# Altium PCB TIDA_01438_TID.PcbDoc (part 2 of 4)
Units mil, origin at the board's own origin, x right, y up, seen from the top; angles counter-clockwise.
Board outline 6250 x 2150 mil, 4 copper layers (Top Layer, V-, V+, Bottom Layer), stack 61.6 mil thick; 360 components, 217 nets, 1141 pads, 401 vias.
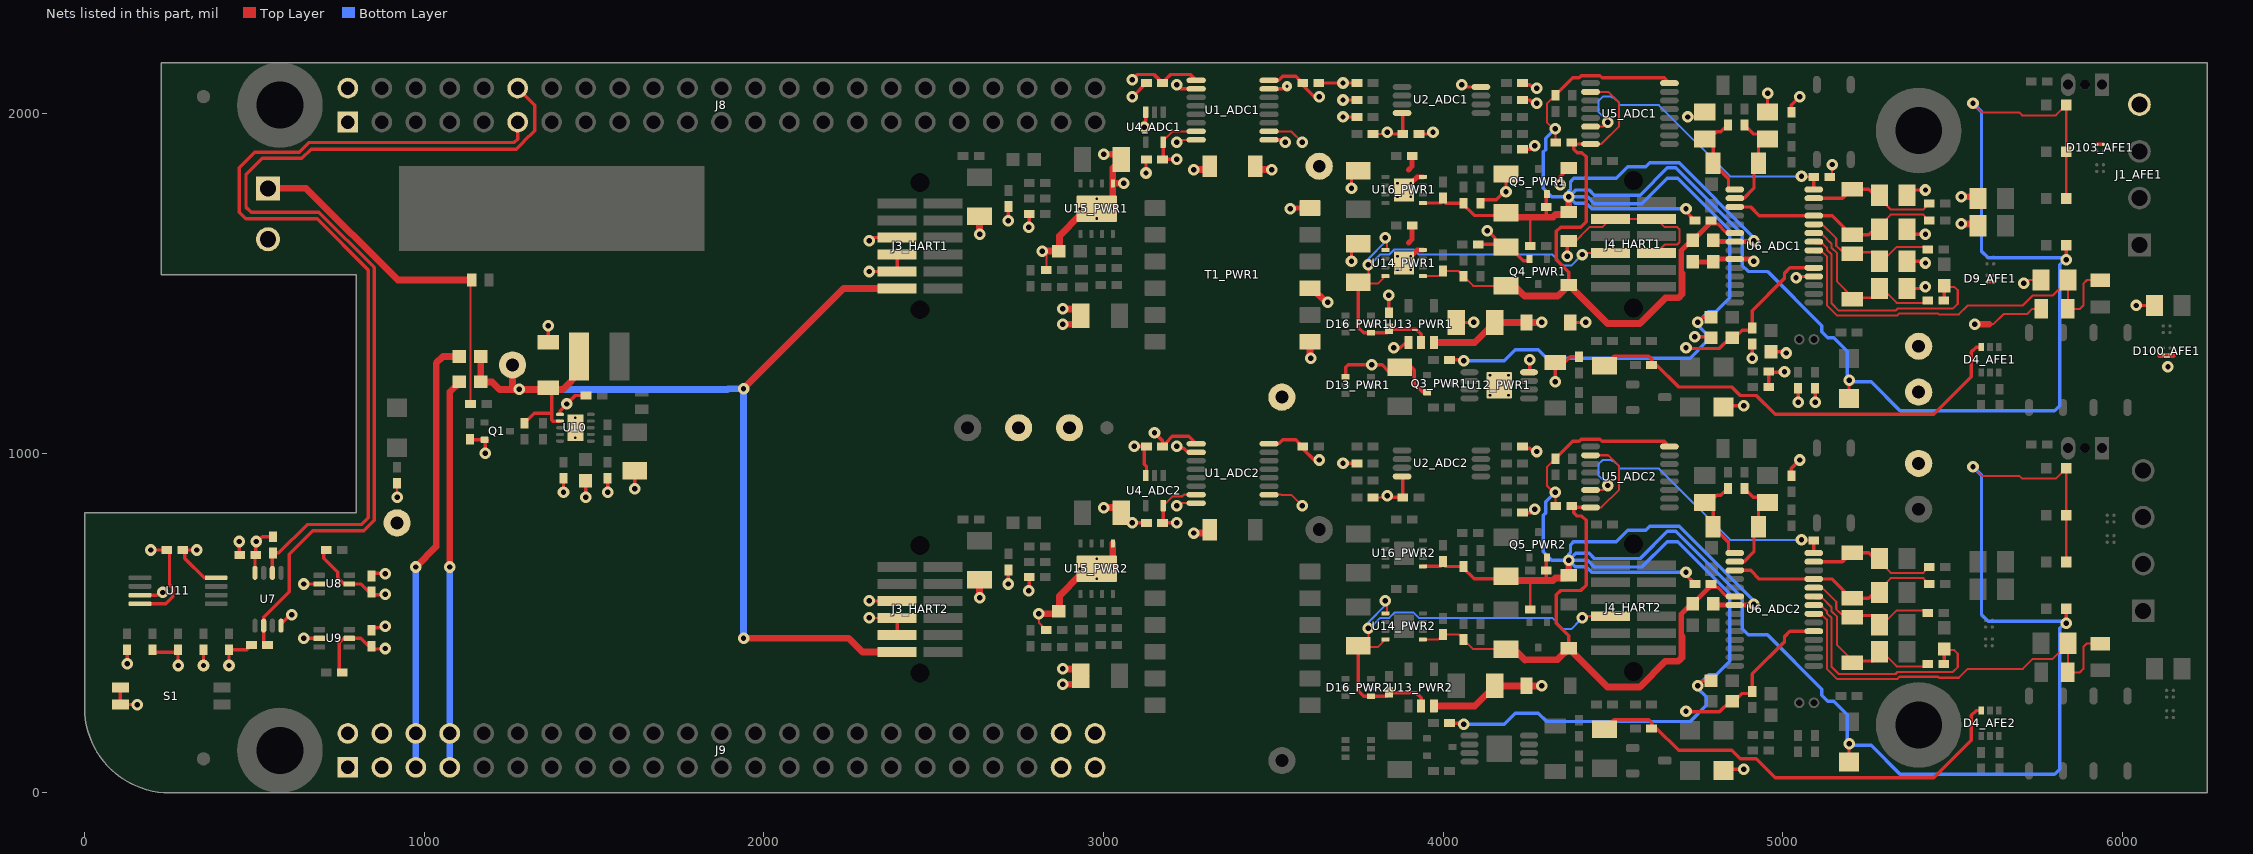
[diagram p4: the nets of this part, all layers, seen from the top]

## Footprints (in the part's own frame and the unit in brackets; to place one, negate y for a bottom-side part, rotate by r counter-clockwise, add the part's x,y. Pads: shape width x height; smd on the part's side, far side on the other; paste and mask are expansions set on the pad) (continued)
Samtec_TFM-106-02-x-D-A [mm] "Header(Shrouded), 1.27mm, 6x2, SMT"
  rect 2.92x0.74 smd: 1(-1.715,3.175) 2(1.715,3.175) 3(-1.715,1.905) 4(1.715,1.905) 5(-1.715,0.635) 6(1.715,0.635) 7(-1.715,-0.635) 8(1.715,-0.635) 9(-1.715,-1.905) 10(1.715,-1.905) 11(-1.715,-3.175) 12(1.715,-3.175)
  round 0 hole 1.42 unplated: MH1(0,4.765) MH2(0,-4.765)
  silkscreen extent -3.2,-5.4 2.86,5.4, body extent -2.98,-5.4 2.98,5.4, height 5.74
SOD-123 [mm] "On Semi recommended land pattern"
  rect 0.915x1.22 smd: 1(-1.637,0) 2(1.637,0)
  silkscreen extent -2.74,-1.17 2.03,1.17, body extent -1.93,-0.9 1.93,0.9, height 1.35
SOT-23 [mm] "SOT23, 3-Leads, Body 2.9x1.3mm, Pitch 0.95mm, Lead Span 2.5mm, IPC Medium Density"
  rrect50% 1x0.6 smd: 1(-1.2,0.95) 2(-1.2,-0.95) 3(1.2,0)
  silkscreen extent -1.63,-1.5 0.7,1.5, body extent -1.16,-1.45 1.21,1.45, height 1
SOT-323 [mm] "Diodes Inc recommended land pattern.  2016-02-24"
  rrect21% 0.6x0.47 smd: 1(-0.95,0.65) 2(-0.95,-0.65) 3(0.95,0)
  silkscreen extent -1.14,-1.22 0.77,1.22, body extent -1.13,-1.13 1.12,1.12, height 1.13
SOT-363 [mm]
  rect 0.6x0.42 smd mask+0.051: 1(-0.95,0.65) 2(-0.95,0) 3(-0.95,-0.65) 4(0.95,-0.65) 5(0.95,0) 6(0.95,0.65)
  silkscreen extent -0.38,-1.02 0.38,1.02, body extent -1.1,-1.1 1.1,1.1, height 1.12
SW_416131160802 [mm] "SMD, 4-Leads, Body 5.6x3.58mm, Pitch 1.27mm"
  rect 1.27x0.76 smd: 1(-3.81,0.635) 2(-3.81,-0.635) 3(3.81,-0.635) 4(3.81,0.635)
  silkscreen extent -2.8,-1.79 2.8,2.1, body extent -4,-1.79 4,1.79, height 2.1
TESTPOINT [mil]
  round 80 hole 37.99: 1(0,0)
TI_Stacked_SolderMask_Small [mil]
  rect 900x250 smd paste-125 mask-125: 0(0,0)
TSSOP-8 [mm] "TSSOP, 8-Leads, Body 3.1x4.5mm (max), Pitch 0.65mm, IPC Medium Density"
  rrect50% 1.7x0.35 smd: 1(-2.85,0.975) 2(-2.85,0.325) 3(-2.85,-0.325) 4(-2.85,-0.975) 5(2.85,-0.975) 6(2.85,-0.325) 7(2.85,0.325) 8(2.85,0.975)
  silkscreen extent -2.98,-1.55 1.6,1.82, body extent -3.2,-1.55 3.2,1.55, height 1.07
WE-LQS_4018 [mm] "SMD, 2-Leads, Body 4x4mm"
  rect 1.5x3.6 smd: 1(-1.525,0) 2(1.525,0)
  silkscreen extent -0.5,-2 0.5,2, body extent -2,-2 2,2, height 1.8
WL_SMCW_GREEN_1206 [mm] "SMD, 2-Leads, Body 3.2x1.6mm, Pitch 3mm"
  rect 1.4x1.5 smd: 1(-1.5,0) 2(1.5,0)
  silkscreen extent -2.9,-1.1 2.2,1.1, body extent -1.6,-0.85 1.6,0.85, height 0.78
WL_SMCW_RED_1206 [mm] "SMD, 2-Leads, Body 3.2x1.6mm, Pitch 3mm"
  rect 1.4x1.5 smd: 1(-1.5,0) 2(1.5,0)
  silkscreen extent -2.9,-1.1 2.2,1.1, body extent -1.6,-0.85 1.6,0.85, height 0.78
Wurth_750315856 [mm] "SMT, 12-Leads, Body 12.85x12.95mm, Pitch 2mm"
  rrect9% 1.57x1.17 smd: 1(-5.79,5) 2(-5.79,3) 3(-5.79,1) 4(-5.79,-1) 5(-5.79,-3) 6(-5.79,-5) 7(5.79,-5) 8(5.79,-3) 9(5.79,-1) 10(5.79,1) 11(5.79,3) 12(5.79,5)
  silkscreen extent -5.3,-6.48 5,6.48, body extent -6.42,-6.47 6.43,6.48, height 6.35
YZF0004-C01 [mm] "BGA, 4-Balls, Body 1.062x1.116mm, Pitch 0.5mm"
  round 0.245 smd paste-0.125: A1(-0.25,0.25) A2(0.25,0.25) B1(-0.25,-0.25) B2(0.25,-0.25)
  silkscreen extent -0.68,-0.65 0.67,0.65, body extent -0.57,-0.55 0.57,0.55, height 0.63

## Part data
C1_ADC1 C1_ADC2 C2_ADC1 C2_ADC2 C3_ADC1 C3_ADC2 C4_ADC1 C4_ADC2 C5_ADC1 C5_ADC2 C7_ADC1 C7_ADC2 C9_ADC1 C9_ADC2 C10_ADC1 C10_ADC2 C26_AFE1 C26_AFE2 C31 C32 C33 C34 C36 C38 C43_PWR1 C43_PWR2 C54_PWR1 C54_PWR2 C56_PWR1 C56_PWR2: "CAP, CERM, 0.1 µF, 50 V, +/- 10%, X7R, 0402"
C6_ADC1 C6_ADC2 C8_ADC1 C8_ADC2 C14_ADC1 C14_ADC2 C15_ADC1 C15_ADC2 C16_ADC1 C16_ADC2 C37: "CAP, CERM, 1 µF, 16 V, +/- 10%, X7R, 0603"
C11_ADC1 C11_ADC2: "CAP, CERM, 4700 pF, 25 V, +/- 5%, C0G/NP0, 0603"
C12_ADC1 C12_ADC2 C13_ADC1 C13_ADC2: "CAP, CERM, 33 pF, 25 V, +/- 5%, C0G/NP0, 0402"
C17_AFE1 C17_AFE2 C19_AFE1 C19_AFE2 C22_AFE1 C22_AFE2 C25_AFE1 C25_AFE2 C28_AFE1 C28_AFE2 C30_AFE1 C30_AFE2: "CAP, CERM, 8200 pF, 50 V, +/- 5%, C0G/NP0, 0805"
C18_AFE1 C18_AFE2 C24_AFE1 C24_AFE2 C29_AFE1 C29_AFE2: "CAP, CERM, 0.1 µF, 50 V, +/- 5%, C0G/NP0, 1206_190"
C20_AFE1 C20_AFE2 C23_AFE1 C23_AFE2 C27_AFE1 C27_AFE2: "CAP, CERM, 0.01 µF, 100 V, +/- 10%, X7R, 0805"
C21_AFE1 C21_AFE2: "CAP, CERM, 5600 pF, 50 V, +/- 5%, C0G/NP0, 0805"
C35 C40_PWR1 C40_PWR2: "CAP, CERM, 4.7 µF, 50 V, +/- 20%, X7R, 1206_190"
C39 C41_PWR1 C41_PWR2 C53_PWR1 C53_PWR2 C55_PWR1 C55_PWR2: "CAP, CERM, 2.2 µF, 50 V, +/- 10%, X7R, 1206"
C42_PWR1 C42_PWR2: "CAP, CERM, 270 pF, 50 V, +/- 10%, X7R, 0402"
C44_PWR1 C44_PWR2 C46_PWR1 C46_PWR2 C47_PWR1 C47_PWR2 C52_PWR1 C52_PWR2 C58_PWR1 C58_PWR2: "CAP, CERM, 10 µF, 16 V, +/- 20%, X7R, 1206"
C45_PWR1 C45_PWR2 C48_PWR1 C48_PWR2 C49_PWR1 C49_PWR2 C51_PWR1 C51_PWR2 C59_PWR1 C59_PWR2: "CAP, CERM, 0.01 µF, 25 V, +/- 10%, X7R, 0402"
C50_PWR1 C50_PWR2: "CAP, CERM, 3300 pF, 50 V, +/- 10%, X7R, 0402"
C57_PWR1 C57_PWR2: "CAP, CERM, 10 µF, 25 V, +/- 10%, X7R, 1206"
C60_PWR1 C60_PWR2: "CAP, CERM, 1 µF, 25 V, +/- 10%, X7R, 0603"
C61_PWR1 C61_PWR2: "CAP, CERM, 1000 pF, 2000 V, +/- 10%, X7R, 1206_190"
D1_ADC1 D1_ADC2 D3_AFE1 D3_AFE2 D6_AFE1 D6_AFE2 D8_AFE1 D8_AFE2: "LED, Blue, SMD"
D2_ADC1 D2_ADC2: "LED, Red, SMD"
D4_AFE1 D4_AFE2 D13_PWR1 D13_PWR2 D16_PWR1 D16_PWR2: "Diode, Schottky, 70 V, 0.07 A, SOT-363"
D5_AFE1 D5_AFE2 D7_AFE1 D7_AFE2 D9_AFE1 D9_AFE2 D100_AFE1 D100_AFE2 D101_AFE1 D101_AFE2 D103_AFE1 D103_AFE2: "33V Precision Surge Protection Clamp, YZF0004-C01 (DSBGA-4)"
D10 D19_PWR1 D19_PWR2 D20: "Diode, Schottky, 35 V, 0.2 A, 0603 Diode"
D11 D12_PWR1 D12_PWR2 D14_PWR1 D14_PWR2: "LED, Green, SMD"
D15_PWR1 D15_PWR2 D17_PWR1 D17_PWR2: "Diode, Zener, 3.6 V, 500 mW, SOD-123"
D18_PWR1 D18_PWR2: "Diode, Zener, 2.7 V, 500 mW, SOD-123"
FID1 FID2 FID3: "Fiducial mark.  There is nothing to buy or mount."
J1_AFE1 J1_AFE2: "Terminal Block, 4x1, 3.5mm, Green, R/A, TH"
J2: "Terminal Block, 2x1, 3.81mm, R/A, TH"
J3_HART1 J3_HART2 J4_HART1 J4_HART2: "Header(Shrouded), 1.27mm, 6x2, Tin, SMT"
J8 J9: "Female Connector, 2.54mm, 23x2, TH"
K1_AFE1 K1_AFE2 K2_AFE1 K2_AFE2 K3_AFE1 K3_AFE2: "Relay, SPST-NO (1 Form A), 0.1 A, 1.2 VDC, SMD"
L1: "Inductor, Wirewound, Ferrite, 10 µH, 1.2 A, 0.15 ohm, SMD"
L2_PWR1 L2_PWR2: "Inductor, Ferrite, 2.2 µH, 0.35 A, 0.38 ohm, SMD"
Logo1: library part TI_Logo, "Texas Instrument Corporate Signature"
Logo2: library part Pb-Free
MH1 MH2 MH3 MH4: library part "Mounting Hole (Imperial) with Pads", "PCB Mounting Hole"
Q1 Q3_PWR1 Q3_PWR2 Q4_PWR1 Q4_PWR2 Q5_PWR1 Q5_PWR2: "MOSFET, N-CH, 60 V, 0.31 A, SOT-323"
Q2_PWR1 Q2_PWR2: library part "BC856A-7-F, Diodes Inc.", "Transistor, PNP, 65 V, 0.01 A, SOT-23"
R1_ADC1 R1_ADC2 R37 R38: "RES, 6.65 k, 1%, 0.063 W, 0402"
R2_ADC1 R2_ADC2 R41: "RES, 261 k, 1%, 0.063 W, 0402"
R3_ADC1 R3_ADC2 R5_ADC1 R5_ADC2 R9_ADC1 R9_ADC2 R10_ADC1 R10_ADC2 R11_ADC1 R11_ADC2 R28 R29 R32 R33 R34 R35 R36 R39 R42 R47_PWR1 R47_PWR2 R51_PWR1 R51_PWR2 R53_PWR1 R53_PWR2 R58_PWR1 R58_PWR2 R61_PWR1 R61_PWR2: "RES, 47 k, 5%, 0.063 W, 0402"
R4_ADC1 R4_ADC2: "RES, 576 k, 1%, 0.063 W, 0402"
R6_ADC1 R6_ADC2: "RES, 340 k, 1%, 0.063 W, 0402"
R7_ADC1 R7_ADC2 R12_ADC1 R12_ADC2: "RES, 1.65 k, 1%, 0.063 W, 0402"
R8_ADC1 R8_ADC2 R45 R50_PWR1 R50_PWR2: "RES, 8.25 k, 1%, 0.063 W, 0402"
R13_ADC1 R13_ADC2: "RES, 475, 1%, 0.063 W, 0402"
R14_AFE1 R14_AFE2 R17_AFE1 R17_AFE2 R21_AFE1 R21_AFE2 R22_AFE1 R22_AFE2 R24_AFE1 R24_AFE2 R26_AFE1 R26_AFE2 R27_AFE1 R27_AFE2 R49_PWR1 R49_PWR2: "RES, 5.11 k, 1%, 0.063 W, 0402"
R15_AFE1 R15_AFE2 R20_AFE1 R20_AFE2 R23_AFE1 R23_AFE2: "RES, 49.9, 1%, 0.063 W, 0402"
R16_AFE1 R16_AFE2: "RES, 4.99 k, 0.01%, 0.1 W, 0603"
R18_AFE1 R18_AFE2: "RES, 82.5 k, 0.1%, 0.1 W, 0805"
R19_AFE1 R19_AFE2: "RES, 17.8 k, 0.1%, 0.1 W, 0805"
R25_AFE1 R25_AFE2: "RES, 27.4, 0.1%, 0.1 W, 0805"
R30 R31: "RES, 0, 5%, 0.1 W, 0603"
R40 R56_PWR1 R56_PWR2 R64_PWR1 R64_PWR2 R69_PWR1 R69_PWR2: "RES, 100 k, 1%, 0.063 W, 0402"
R43: "RES, 200 k, 1%, 0.063 W, 0402"
R44: "RES, 8.06 k, 1%, 0.063 W, 0402"
R46_PWR1 R46_PWR2: "RES, 20.5, 1%, 0.25 W, 1206"
R48_PWR1 R48_PWR2 R52_PWR1 R52_PWR2: "RES, 953 k, 1%, 0.063 W, 0402"
R54_PWR1 R54_PWR2: "RES, 931, 1%, 0.063 W, 0402"
R55_PWR1 R55_PWR2 R60_PWR1 R60_PWR2: "RES, 113 k, 1%, 0.063 W, 0402"
R57_PWR1 R57_PWR2 R59_PWR1 R59_PWR2: "RES, 169 k, 1%, 0.063 W, 0402"
R62_PWR1 R62_PWR2: "RES, 1.0, 5%, 0.063 W, 0402"
R63_PWR1 R63_PWR2: "RES, 422 k, 1%, 0.063 W, 0402"
R65_PWR1 R65_PWR2: "RES, 54.9 k, 1%, 0.063 W, 0402"
R66_PWR1 R66_PWR2: "RES, 73.2 k, 1%, 0.063 W, 0402"
R67_PWR1 R67_PWR2: "RES, 8.66 k, 1%, 0.063 W, 0402"
R68_PWR1 R68_PWR2: "RES, 7.68 k, 1%, 0.063 W, 0402"
S1: "Switch, SPST, Off-On, 2 Pos, SMD"
T1_PWR1 T1_PWR2: "Transformer, 120 uH, SMT"
TP1_ADC1 TP1_ADC2 TP2 TP3 TP4_AFE1 TP4_AFE2 TP5_AFE1 TP5_AFE2 TP6_AFE1 TP6_AFE2 TP7 TP8 TP10: "TEST POINT.  No entry in BOM."
U1_ADC1 U1_ADC2: "4242-VPK Small-Footprint and Low-Power Quad Channels Digital Isolators, DBQ0016A"
U2_ADC1 U2_ADC2: "Dual Comparator, PW0008A"
U3_ADC1 U3_ADC2: "0.5°C Accurate 2-Pin Digital NTC or PTC Thermistor Replacement, LPG0002A"
U4_ADC1 U4_ADC2: "Single Bus Buffer Gate With 3-State Output, DCK0005A"
U5_ADC1 U5_ADC2: "8-Bit Shift Register With Output Registers, PW0016A"
U6_ADC1 U6_ADC2: "32-Bit, Precision, 38-kSPS, Analog-to-Digital Converter (ADC) with Programmable Gain Amplifier (PGA) and Voltage Reference, PW0028A"
U7: "Dual 2-Input Exclusive-OR Gate, DCT0008A"
U8 U9: "Single 3-Input Positive-OR Gate, DCK0006A"
U10: "LOW INPUT BOOST CONVERTER WITH INTEGRATED POWER DIODE AND INPUT/OUTPUT ISOLATION, DSK0010A"
U11: "256K I2C CMOS Serial EEPROM, TSSOP-8"
U12_PWR1 U12_PWR2: "Single Output LDO, 50 mA, Adjustable 1.175 to 48 V Output, 7 to 50 V Input, 8-pin MSOP (DGN), -40 to 125 degC, Green (RoHS & no Sb/Br)"
U13_PWR1 U13_PWR2: "Single Output LDO, 150 mA, Fixed 3.3 V Output, 2.5 to 24 V Input, with Ultra-Low IQ, 5-pin SOT-23 (DBV), -40 to 125 degC, Green (RoHS & no Sb/Br)"
U14_PWR1 U14_PWR2: "+36V, +150mA, Ultralow-Noise, Positive LINEAR REGULATOR, DRB0008A"
U15_PWR1 U15_PWR2: "100V, 600mA Constant On-Time Synchronous Buck Regulator, NGU0008B"
U16_PWR1 U16_PWR2: "-35-V, -200-mA, Ultralow-Noise, Negative Linear Regulator, DRB0008A"
Y1_ADC1 Y1_ADC2: "Crystal, 7.3728MHz, 18pF, SMD"
ZZ1 ZZ2 ZZ3: library part AssemblyNote

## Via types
v1: diameter 34, hole 16, Top Layer to Bottom Layer, 337 vias
v2: diameter 19.68, hole 7.87, Top Layer to Bottom Layer, 36 vias
v3: diameter 39.37, hole 19.68, Top Layer to Bottom Layer, 24 vias
v4: diameter 30, hole 10, Top Layer to Bottom Layer, 4 vias

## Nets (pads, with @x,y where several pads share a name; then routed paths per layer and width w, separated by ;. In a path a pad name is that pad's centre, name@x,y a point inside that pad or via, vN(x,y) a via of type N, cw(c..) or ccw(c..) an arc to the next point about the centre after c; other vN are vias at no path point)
"4-20MA LOOP_AFE1": D4_AFE1.3 R46_PWR1.1 R49_PWR1.2 | length 1325.5
  Top Layer w10: R46_PWR1.1@4475,1257.09 4502.91,1285 4605,1285 4613.62,1276.38 R49_PWR1.2@4613.62,1260 4628,1260 4693,1195 4850,1195 4875,1170 4922.26,1170 4977.26,1115 5445,1115 5555,1225 5555,1297.99 5569.41,1312.4 D4_AFE1.3@5584.41,1312.4
"4-20MA LOOP_AFE2": D4_AFE2.3 R46_PWR2.1 R49_PWR2.2 | length 1325.5
  Top Layer w10: R46_PWR2.1@4475,187.09 4502.91,215 4605,215 4613.62,206.38 R49_PWR2.2@4613.62,190 4628,190 4693,125 4850,125 4875,100 4922.26,100 4977.26,45 5445,45 5555,155 5555,227.99 5569.41,242.4 D4_AFE2.3@5584.41,242.4
+5V: C35.1 J3_HART1.11 J3_HART2.11 L1.1 R30.1 R31.1 R39.2 TP2.1 U10.2 | length 3125.2
  Top Layer w10: R39.2@1295,1088.62 1323.62,1117.24 1372.76,1117.24 1375,1115 ; C35.1@1387.91,1187.91 1375.04,1175.04 1375.04,1099.16 1374.68,1098.8 1378.8,1094.69 U10.2@1399.72,1094.69
  Top Layer w20: R30.1@1166.5,1285 R31.1@1166.5,1210 1200,1210 1222.09,1187.91 1260,1187.91 ; TP2.1@1260,1260 1260,1187.91 ; L1.1@1460.09,1240.09 1407.91,1187.91 1387.91,1187.91 v1(1280,1187.91) 1260,1187.91 ; v1(1940,455) 2250,455 2290,415 J3_HART2.11@2392.48,415 ; v1(1940,1190) 2235,1485 J3_HART1.11@2392.48,1485
  Bottom Layer w20: v1(1280,1187.91) 1892.91,1187.91 1895,1190 v1(1940,1190) v1(1940,455)
+5V_ISO_HART1: C43_PWR1.1 C47_PWR1.1 D16_PWR1.4 J4_HART1.7 U13_PWR1.2 U14_PWR1.5 U14_PWR1.8 | length 1445.1
  Top Layer w6: v1(3780,1555) 3780,1521.61 3780,1505 3775,1500 3808.27,1500 U14_PWR1.8@3829.88,1521.61 ; U14_PWR1.5@3829.88,1598.39 3835,1603.5 3835,1635 3832.87,1632.87 3830,1635.75 3829.25,1635 v1(3830,1635) ; v1(4410,1585) 4415,1590 J4_HART1.7@4492.48,1590
  Top Layer w10: C47_PWR1.1@3780,1521.61 3768.7,1521.61 C47_PWR1.1@3750,1502.91 3750,1370 3765.59,1354.41 D16_PWR1.4@3787.4,1354.41 3835.91,1354.41 C43_PWR1.1@3840,1358.5 ; C43_PWR1.1@3840,1366.38 3841.38,1365 3920,1365 3935,1350 U13_PWR1.2@3935,1325.87
  Bottom Layer w6: v1(3830,1635) 3830,1632.89 3825,1627.89 3830,1622.89 3780,1572.89 3780,1550 3815,1585 3841.33,1585 3856.73,1600.4 3913.27,1600.4 3928.67,1585 4320.58,1585 4353.45,1552.13 4376.55,1552.13 4404.42,1580 4404.42,1585 v1(4410,1585)
+5V_ISO_HART2: C43_PWR2.1 C47_PWR2.1 D16_PWR2.4 J4_HART2.7 U13_PWR2.2 U14_PWR2.5 U14_PWR2.8 | length 1445.1
  Top Layer w6: v1(3780,485) 3780,451.61 3780,435 3775,430 3808.27,430 U14_PWR2.8@3829.88,451.61 ; U14_PWR2.5@3829.88,528.39 3835,533.5 3835,565 3832.87,562.87 3830,565.75 3829.25,565 v1(3830,565) ; v1(4410,515) 4415,520 J4_HART2.7@4492.48,520
  Top Layer w10: C47_PWR2.1@3780,451.61 3768.7,451.61 C47_PWR2.1@3750,432.91 3750,300 3765.59,284.41 D16_PWR2.4@3787.4,284.41 3835.91,284.41 C43_PWR2.1@3840,288.5 ; C43_PWR2.1@3840,296.38 3841.38,295 3920,295 3935,280 U13_PWR2.2@3935,255.87
  Bottom Layer w6: v1(3830,565) 3830,562.89 3825,557.89 3830,552.89 3780,502.89 3780,480 3815,515 3841.33,515 3856.73,530.4 3913.27,530.4 3928.67,515 4320.58,515 4353.45,482.13 4376.55,482.13 4404.42,510 4404.42,515 v1(4410,515)
+5V_JACK: J9.5 J9.6 R30.2 | length 1291.6
  Top Layer w20: v1(975,665) 1035,725 1035,1265 1055,1285 R30.2@1103.5,1285
  Bottom Layer w20: J9.5@975,75 J9.6@975,175 v1(975,665)
+5V_JACK_USB: J9.7 J9.8 R31.2 | length 1146.8
  Top Layer w20: v1(1075,665) 1075,1180 1103.5,1208.5 R31.2@1103.5,1210
  Bottom Layer w20: J9.7@1075,75 J9.8@1075,175 v1(1075,665)
+24V: D20.2 J2.1 R40.2 | length 1077.9
  Top Layer w6: R40.2@1136.38,1145 1135.94,1145.44 1135.94,1261.8 1135.94,1506.53 D20.2@1139.41,1510
  Top Layer w20: J2.1@540,1780 652.12,1780 922.12,1510 D20.2@1139.41,1510
AIN0_ADC1: C21_AFE1.1 R18_AFE1.2 R19_AFE1.2 U6_ADC1.21 | length 1212.9
  Top Layer w6: U6_ADC1.21@5091.14,1597.2 5097,1591.35 5118.02,1591.35 5129.57,1579.79 5129.57,1435.8 5160.38,1405 5336.45,1405 5343.31,1411.86 5456.69,1411.86 5459.69,1408.86 5518.48,1408.86 5544.62,1435 5707.02,1435 5736.44,1464.42 5794.42,1464.42 C21_AFE1.1@5840,1510 5840,1425.63 R19_AFE1.2@5839.37,1425 5875,1425 5885,1435 5885,1499.37 5895.63,1510 5934.37,1510 R18_AFE1.2@5935,1509.37
AIN0_ADC2: C21_AFE2.1 R18_AFE2.2 R19_AFE2.2 U6_ADC2.21 | length 1212.9
  Top Layer w6: U6_ADC2.21@5091.14,527.2 5097,521.35 5118.02,521.35 5129.57,509.79 5129.57,365.8 5160.38,335 5336.45,335 5343.31,341.86 5456.69,341.86 5459.69,338.86 5518.48,338.86 5544.62,365 5707.02,365 5736.44,394.42 5794.42,394.42 C21_AFE2.1@5840,440 5840,355.63 R19_AFE2.2@5839.37,355 5875,355 5885,365 5885,429.37 5895.63,440 5934.37,440 R18_AFE2.2@5935,439.37
AIN1_ADC1: R14_AFE1.1 R16_AFE1.2 U6_ADC1.22 | length 733.7
  Top Layer w6: U6_ADC1.22@5091.14,1622.8 5097,1616.94 5118.02,1616.94 5129.57,1605.38 5129.57,1599.41 5143.45,1585.53 5143.45,1441.55 5165,1420 5331.83,1420 5337.56,1425.73 5500.73,1425.73 5515,1440 5515,1480 5505,1490 5478.5,1490 R16_AFE1.2@5475,1493.5
  Top Layer w10: R14_AFE1.1@5473.62,1450 5475,1451.38 R16_AFE1.2@5475,1493.5
AIN1_ADC2: R14_AFE2.1 R16_AFE2.2 U6_ADC2.22 | length 733.7
  Top Layer w6: U6_ADC2.22@5091.14,552.8 5097,546.94 5118.02,546.94 5129.57,535.38 5129.57,529.41 5143.45,515.53 5143.45,371.55 5165,350 5331.83,350 5337.56,355.73 5500.73,355.73 5515,370 5515,410 5505,420 5478.5,420 R16_AFE2.2@5475,423.5
  Top Layer w10: R14_AFE2.1@5473.62,380 5475,381.38 R16_AFE2.2@5475,423.5
AIN2_ADC1: C17_AFE1.1 C18_AFE1.1 R14_AFE1.2 U6_ADC1.23 | length 539.3
  Top Layer w6: U6_ADC1.23@5091.14,1648.39 5097,1642.53 5118.02,1642.53 5129.57,1630.97 5129.57,1630.43 5143.45,1616.55 5143.45,1605.15 5160,1588.6 5160,1505 5205,1460 5205,1458.07 C18_AFE1.1@5205,1453.07 ; C17_AFE1.1@5285,1475 C17_AFE1.1@5285,1485 5293.12,1485 5335.5,1442.63 5426.38,1442.63 R14_AFE1.2@5426.38,1450
  Top Layer w8: U6_ADC1.23@5091.14,1648.39 U6_ADC1.23@5112.29,1648.39 ; C18_AFE1.1@5205,1458.07 5268.07,1458.07 C17_AFE1.1@5285,1475
AIN2_ADC2: C17_AFE2.1 C18_AFE2.1 R14_AFE2.2 U6_ADC2.23 | length 539.3
  Top Layer w6: U6_ADC2.23@5091.14,578.39 5097,572.53 5118.02,572.53 5129.57,560.97 5129.57,560.43 5143.45,546.55 5143.45,535.15 5160,518.6 5160,435 5205,390 5205,388.07 C18_AFE2.1@5205,383.07 ; C17_AFE2.1@5285,405 C17_AFE2.1@5285,415 5293.12,415 5335.5,372.63 5426.38,372.63 R14_AFE2.2@5426.38,380
  Top Layer w8: U6_ADC2.23@5091.14,578.39 U6_ADC2.23@5112.29,578.39 ; C18_AFE2.1@5205,388.07 5268.07,388.07 C17_AFE2.1@5285,405
AIN3_ADC1: C18_AFE1.2 C19_AFE1.2 R17_AFE1.2 U6_ADC1.24 | length 471.1
  Top Layer w6: U6_ADC1.24@5091.14,1673.98 5092.17,1675 5115,1675 5157.32,1632.68 5157.32,1610.9 5171.2,1597.03 5197.87,1597.03 C18_AFE1.2@5204.45,1590.45 ; C19_AFE1.2@5285,1565 5293.12,1565 5335.5,1607.37 5426.38,1607.37 R17_AFE1.2@5426.38,1600
  Top Layer w8: U6_ADC1.24@5091.14,1673.98 U6_ADC1.24@5113.57,1673.98 ; C18_AFE1.2@5205,1591.93 5266.59,1591.93 C19_AFE1.2@5285,1573.52 ; C19_AFE1.2@5285,1565 5305,1585 C19_AFE1.2@5305,1590
AIN3_ADC2: C18_AFE2.2 C19_AFE2.2 R17_AFE2.2 U6_ADC2.24 | length 471.1
  Top Layer w6: U6_ADC2.24@5091.14,603.98 5092.17,605 5115,605 5157.32,562.68 5157.32,540.9 5171.2,527.03 5197.87,527.03 C18_AFE2.2@5204.45,520.45 ; C19_AFE2.2@5285,495 5293.12,495 5335.5,537.37 5426.38,537.37 R17_AFE2.2@5426.38,530
  Top Layer w8: U6_ADC2.24@5091.14,603.98 U6_ADC2.24@5113.57,603.98 ; C18_AFE2.2@5205,521.93 5266.59,521.93 C19_AFE2.2@5285,503.52 ; C19_AFE2.2@5285,495 5305,515 C19_AFE2.2@5305,520
AIN4_ADC1: C22_AFE1.1 C24_AFE1.1 R21_AFE1.2 U6_ADC1.3 U6_ADC1.25 | length 630
  Top Layer w6: C22_AFE1.1@5285,1660 5285,1670 5317.37,1702.37 5414,1702.37 5430,1686.38 R21_AFE1.2@5430,1683.62
  Top Layer w10: U6_ADC1.3@4858.86,1725.16 4859.02,1725 4905,1725 4930.43,1699.57 U6_ADC1.25@5091.14,1699.57 5145.43,1699.57 5201.91,1643.09 5253.09,1643.09 C22_AFE1.1@5270.02,1660.01
AIN4_ADC2: C22_AFE2.1 C24_AFE2.1 R21_AFE2.2 U6_ADC2.3 U6_ADC2.25 | length 630
  Top Layer w6: C22_AFE2.1@5285,590 5285,600 5317.37,632.37 5414,632.37 5430,616.38 R21_AFE2.2@5430,613.62
  Top Layer w10: U6_ADC2.3@4858.86,655.16 4859.02,655 4905,655 4930.43,629.57 U6_ADC2.25@5091.14,629.57 5145.43,629.57 5201.91,573.09 5253.09,573.09 C22_AFE2.1@5270.02,590.01
AIN6_ADC1: C24_AFE1.2 C25_AFE1.2 R22_AFE1.2 U6_ADC1.27 | length 374.5
  Top Layer w6: C25_AFE1.2@5285,1760 5285,1750 5317.37,1717.63 5414,1717.63 5430,1733.62 R22_AFE1.2@5430,1736.38
  Top Layer w10: U6_ADC1.27@5091.14,1750.75 5175.75,1750.75 5201.94,1776.94 5253.09,1776.94 C25_AFE1.2@5270.01,1760.01
AIN6_ADC2: C24_AFE2.2 C25_AFE2.2 R22_AFE2.2 U6_ADC2.27 | length 374.5
  Top Layer w6: C25_AFE2.2@5285,690 5285,680 5317.37,647.63 5414,647.63 5430,663.62 R22_AFE2.2@5430,666.38
  Top Layer w10: U6_ADC2.27@5091.14,680.75 5175.75,680.75 5201.94,706.94 5253.09,706.94 C25_AFE2.2@5270.01,690.01
AIN7_ADC1: R27_AFE1.2 U5_ADC1.14 U6_ADC1.28 | length 950.4
  Top Layer w6: U5_ADC1.14@4433.86,1961.61 U5_ADC1.14@4438.86,1961.61 ; U5_ADC1.14@4433.86,1966.61 U5_ADC1.14@4438.86,1961.61 ; v1@4485,1968.23 v1(4485,1975) 4471.61,1961.61 U5_ADC1.14@4438.86,1961.61 ; v1(5055,1815) 5050,1815 5052.24,1812.76 R27_AFE1.2@5091.38,1812.76
  Top Layer w10: U6_ADC1.28@5091.14,1776.34 5091.14,1812.52 R27_AFE1.2@5091.38,1812.76
  Bottom Layer w6: v1@4478.45,1981.55 4480,1980 4480,1970 v1(4485,1975) 4485,1977.71 4457.13,2005.58 4457.13,2037.13 4470,2050 4495,2050 4497.13,2047.87 4501.55,2047.87 4517.87,2031.55 4517.87,2027.13 4520,2025 4635,2025 4845,1815 v1(5055,1815)
AIN7_ADC2: R27_AFE2.2 U5_ADC2.14 U6_ADC2.28 | length 950.4
  Top Layer w6: U5_ADC2.14@4433.86,891.61 U5_ADC2.14@4438.86,891.61 ; U5_ADC2.14@4433.86,896.61 U5_ADC2.14@4438.86,891.61 ; v1@4485,898.23 v1(4485,905) 4471.61,891.61 U5_ADC2.14@4438.86,891.61 ; v1(5055,745) 5050,745 5052.24,742.76 R27_AFE2.2@5091.38,742.76
  Top Layer w10: U6_ADC2.28@5091.14,706.34 5091.14,742.52 R27_AFE2.2@5091.38,742.76
  Bottom Layer w6: v1@4478.45,911.55 4480,910 4480,900 v1(4485,905) 4485,907.71 4457.13,935.58 4457.13,967.13 4470,980 4495,980 4497.13,977.87 4501.55,977.87 4517.87,961.55 4517.87,957.13 4520,955 4635,955 4845,745 v1(5055,745)
AIN8_ADC1: C28_AFE1.1 C29_AFE1.1 R24_AFE1.2 U6_ADC1.1 | length 270.4
  Top Layer w6: C29_AFE1.1@4794.64,1853.77 C29_AFE1.1@4810,1838.42
  Top Layer w10: C28_AFE1.1@4775,1925 C28_AFE1.1@4780,1925 ; C29_AFE1.1@4794.64,1853.77 4794.64,1910.36 C28_AFE1.1@4780,1925 ; C29_AFE1.1@4810,1838.42 4840,1808.42 4840,1780 4843.66,1776.34 U6_ADC1.1@4858.86,1776.34 ; R24_AFE1.2@4838,1966.38 4817.84,1946.22 4805,1946.22 4783.78,1925 C28_AFE1.1@4780,1925
AIN8_ADC2: C28_AFE2.1 C29_AFE2.1 R24_AFE2.2 U6_ADC2.1 | length 270.4
  Top Layer w6: C29_AFE2.1@4794.64,783.77 C29_AFE2.1@4810,768.42
  Top Layer w10: C28_AFE2.1@4775,855 C28_AFE2.1@4780,855 ; C29_AFE2.1@4794.64,783.77 4794.64,840.36 C28_AFE2.1@4780,855 ; C29_AFE2.1@4810,768.42 4840,738.42 4840,710 4843.66,706.34 U6_ADC2.1@4858.86,706.34 ; R24_AFE2.2@4838,896.38 4817.84,876.22 4805,876.22 4783.78,855 C28_AFE2.1@4780,855
AIN9_ADC1: C29_AFE1.2 C30_AFE1.2 R26_AFE1.2 U6_ADC1.2 | length 313.6
  Top Layer w10: U6_ADC1.2@4858.86,1750.75 4885.75,1750.75 4915,1780 4915,1840.28 C29_AFE1.2@4928.5,1853.77 4928.5,1901.85 C30_AFE1.2@4951.65,1925 ; R26_AFE1.2@4887,1966.38 4913.38,1940 4925,1940 C30_AFE1.2@4940,1925 ; C30_AFE1.2@4935,1925 C30_AFE1.2@4950,1925
AIN9_ADC2: C29_AFE2.2 C30_AFE2.2 R26_AFE2.2 U6_ADC2.2 | length 313.6
  Top Layer w10: U6_ADC2.2@4858.86,680.75 4885.75,680.75 4915,710 4915,770.28 C29_AFE2.2@4928.5,783.77 4928.5,831.85 C30_AFE2.2@4951.65,855 ; R26_AFE2.2@4887,896.38 4913.38,870 4925,870 C30_AFE2.2@4940,855 ; C30_AFE2.2@4935,855 C30_AFE2.2@4950,855
AVDD_ISO_ADC1: C5_ADC1.1 C8_ADC1.1 C9_ADC1.1 C45_PWR1.1 C46_PWR1.1 D17_PWR1.1 R55_PWR1.2 U5_ADC1.10 U5_ADC1.16 U6_ADC1.6 U14_PWR1.1 | length 2092.9
  Top Layer w6: U14_PWR1.1@3940.12,1521.61 3985.24,1521.61 C45_PWR1.1@4000,1536.38 4045,1536.38 R55_PWR1.2@4060,1521.38 4088.46,1492.91 C46_PWR1.1@4185,1492.91 ; U5_ADC1.16@4433.86,1910.43 4465.43,1910.43 4517.87,1962.87 4517.87,2031.55 4485.44,2063.98 U5_ADC1.10@4433.86,2063.98
  Top Layer w10: D17_PWR1.1@4370,1495.53 4370,1532.75 4333.11,1569.64 4333.11,1653.11 4345.77,1665.77 4405.1,1665.77 4420.76,1681.44 4420.76,1872.86 4408.62,1885 4395,1885 4385,1895 C5_ADC1.1@4385,1910.43 ; C5_ADC1.1@4378.62,1915 4383.19,1910.43 C5_ADC1.1@4385,1910.43 ; C5_ADC1.1@4385,1915 C5_ADC1.1@4385,1910.43 ; U5_ADC1.16@4433.86,1910.43 C5_ADC1.1@4385,1910.43 ; C9_ADC1.1@4783.62,1680 4788.62,1675 4808.4,1675 4831.16,1652.24 4855,1652.24 U6_ADC1.6@4858.86,1648.39
  Top Layer w15: 4700.93,1530 4700.93,1596.51 4735,1630.58 C8_ADC1.1@4735,1631.5 ; C8_ADC1.1@4735,1626.5 4735,1626.62 4783.62,1675.25 C9_ADC1.1@4783.62,1680
  Top Layer w20: C46_PWR1.1@4185,1492.91 4210.09,1492.91 4240,1463 4337.47,1463 D17_PWR1.1@4370,1495.53 4483.96,1381.57 4578.98,1381.57 4654.97,1457.56 4692.4,1457.56 4702.87,1468.03 4702.87,1530
AVDD_ISO_ADC2: C5_ADC2.1 C8_ADC2.1 C9_ADC2.1 C45_PWR2.1 C46_PWR2.1 D17_PWR2.1 R55_PWR2.2 U5_ADC2.10 U5_ADC2.16 U6_ADC2.6 U14_PWR2.1 | length 2093.7
  Top Layer w6: U14_PWR2.1@3940.12,451.61 3985.24,451.61 C45_PWR2.1@4000,466.38 4045,466.38 R55_PWR2.2@4060,451.38 4088.46,422.91 C46_PWR2.1@4185,422.91 ; U5_ADC2.16@4433.86,840.43 4465.43,840.43 4517.87,892.87 4517.87,961.55 4485.44,993.98 U5_ADC2.10@4433.86,993.98
  Top Layer w10: D17_PWR2.1@4370,425.55 4370,462.75 4333.11,499.64 4333.11,583.11 4345.77,595.77 4405.1,595.77 4420.76,611.44 4420.76,802.86 4408.62,815 4395,815 4385,825 C5_ADC2.1@4385,840.43 ; C5_ADC2.1@4378.62,845 4383.19,840.43 C5_ADC2.1@4385,840.43 ; C5_ADC2.1@4385,845 C5_ADC2.1@4385,840.43 ; U5_ADC2.16@4433.86,840.43 C5_ADC2.1@4385,840.43 ; C9_ADC2.1@4783.62,610 4788.62,605 4808.4,605 4831.16,582.24 4855,582.24 U6_ADC2.6@4858.86,578.39
  Top Layer w15: 4700.93,460 4700.93,526.51 4735,560.58 C8_ADC2.1@4735,561.5 ; C8_ADC2.1@4735,556.5 4735,556.62 4783.62,605.25 C9_ADC2.1@4783.62,610
  Top Layer w20: C46_PWR2.1@4185,422.91 C46_PWR2.1@4210.59,422.91 ; C46_PWR2.1@4210.09,421.91 4241,391 ; 4241.5,392 4336.47,392 D17_PWR2.1@4370,425.55 4483.96,311.57 4578.98,311.57 4654.97,387.56 4692.4,387.56 4702.87,398.03 4702.87,460
AVSS_ISO_ADC1: C5_ADC1.2 C9_ADC1.2 C10_ADC1.2 C14_ADC1.1 C15_ADC1.2 C51_PWR1.1 C52_PWR1.1 D1_ADC1.2 D2_ADC1.1 D3_AFE1.2 D6_AFE1.2 D8_AFE1.2 D18_PWR1.2 Q5_PWR1.2 R51_PWR1.1 R58_PWR1.2 R60_PWR1.2 R61_PWR1.2 U5_ADC1.8 U6_ADC1.7 U16_PWR1.1 | length 8258.2
  Top Layer w6: 4255,1695 4256.38,1693.62 R58_PWR1.2@4256.38,1610 ; C10_ADC1.2@4330,2053.62 4305,2028.62 4305,1975 4331.38,1948.62 C5_ADC1.2@4331.38,1915 ; v1(5560,2030) 5560,2029.62 5586.28,2003.34 5696.66,2003.34 5705,1995 5804.13,1995 D1_ADC1.2@5834.53,2025.4 D8_AFE1.2@5834.53,1887.6 D6_AFE1.2@5834.53,1750
  Top Layer w10: U16_PWR1.1@3940.12,1736.61 3993.11,1736.61 4000,1743.5 4007.13,1736.38 4055,1736.38 4091.38,1700 4167.09,1700 C52_PWR1.1@4180,1712.91 ; R51_PWR1.1@4018.62,1275 4060,1275 v1(4060,1272.13) ; C52_PWR1.1@4185,1705 C52_PWR1.1@4185,1707.91 ; 4305,1695 4303.62,1696.38 R61_PWR1.2@4303.62,1725 4303.62,1766.54 Q5_PWR1.2@4305.59,1768.5 ; C10_ADC1.2@4330,2053.62 4381.38,2105 4399.86,2105 4406.16,2111.3 4461.56,2111.3 4467.86,2105 4650.71,2105 U5_ADC1.8@4666.14,2089.57 ; v1(4715,1720) 4715,1718.62 4711.38,1715 C9_ADC1.2@4741.38,1685 ; v1(4750,1385) 4765,1400 C15_ADC1.2@4788.5,1400 ; D2_ADC1.1@5195,1160.94 v1(5195,1215) ; D3_AFE1.2@5834.53,1612.01 5835,1611.54 v1(5835,1570)
  Top Layer w15: C14_ADC1.1@4795,1626.5 4798.7,1622.8 U6_ADC1.7@4858.86,1622.8 v1@4907.2,1622.8
  Top Layer w20: C52_PWR1.1@4185,1707.91 4197.09,1707.91 4210,1695 4255,1695 4305,1695 4323.03,1695 4330.55,1702.52 4361.99,1702.52 D18_PWR1.2@4370,1710.53 v1(4370,1755)
  Bottom Layer w10: v1(4060,1272.13) 4179.88,1272.13 4212.63,1304.87 4280.13,1304.87 4304.87,1280.13 4727.37,1280.13 4774.87,1327.63 4774.87,1352.37 4750,1377.25 v1(4750,1385) 4782.38,1417.38 4803.87,1417.38 4843.75,1457.26 4843.75,1656.25 4690.13,1809.87 4659.87,1809.87 4585,1735 4445,1735 4425,1755 v1(4370,1755) ; v1(4330,1955) 4301.77,1926.77 4301.77,1894.02 4295.13,1887.37 4295.13,1779.87 4320,1755 v1(4370,1755) ; v1(4715,1720) 4437.45,1720 4421.58,1735.87 4389.13,1735.87 v1(4370,1755) ; v1(4915,1625) 4915,1635 4695,1855 4608.51,1855 4596.94,1843.43 4543.09,1843.43 4509.54,1809.87 4385.13,1809.87 4385,1810 4375,1800 4375,1777.75 4370,1772.75 v1(4370,1755) ; v1(5560,2030) 5585,2005 5585,1595 5605,1575 5835,1575 5814.87,1554.87 5814.87,1139.87 5800,1125 5345,1125 5260,1210 5200,1210 v1(5195,1215) 5190.13,1210.13 5190.13,1299.87 5149.87,1340.13 5132.63,1340.13 5115.13,1357.63 5115.13,1374.87 4954.87,1535.13 4897.63,1535.13 4880.13,1552.63 4880.13,1644.87 4685,1840 4660,1840 4580,1760 4445,1760 4430,1775 4390,1775 v1(4370,1755)
AVSS_ISO_ADC2: C5_ADC2.2 C9_ADC2.2 C10_ADC2.2 C14_ADC2.1 C15_ADC2.2 C51_PWR2.1 C52_PWR2.1 D1_ADC2.2 D2_ADC2.1 D3_AFE2.2 D6_AFE2.2 D8_AFE2.2 D18_PWR2.2 Q5_PWR2.2 R51_PWR2.1 R58_PWR2.2 R60_PWR2.2 R61_PWR2.2 U5_ADC2.8 U6_ADC2.7 U16_PWR2.1 | length 8258.2
  Top Layer w6: 4255,625 4256.38,623.62 R58_PWR2.2@4256.38,540 ; C10_ADC2.2@4330,983.62 4305,958.62 4305,905 4331.38,878.62 C5_ADC2.2@4331.38,845 ; v1(5560,960) 5560,959.62 5586.28,933.34 5696.66,933.34 5705,925 5804.13,925 D1_ADC2.2@5834.53,955.39 D8_AFE2.2@5834.53,817.56 D6_AFE2.2@5834.53,679.97
  Top Layer w10: U16_PWR2.1@3940.12,666.61 3993.11,666.61 4000,673.5 4007.13,666.38 4055,666.38 4091.38,630 4167.09,630 C52_PWR2.1@4180,642.91 ; R51_PWR2.1@4018.62,205 4060,205 v1(4060,202.13) ; C52_PWR2.1@4185,635 C52_PWR2.1@4185,637.91 ; 4305,625 4303.62,626.38 R61_PWR2.2@4303.62,655 4303.62,696.54 Q5_PWR2.2@4305.59,698.5 ; C10_ADC2.2@4330,983.62 4381.38,1035 4399.86,1035 4406.16,1041.3 4461.56,1041.3 4467.86,1035 4650.71,1035 U5_ADC2.8@4666.14,1019.57 ; v1(4715,650) 4715,648.62 4711.38,645 C9_ADC2.2@4741.38,615 ; v1(4750,315) 4765,330 C15_ADC2.2@4788.5,330 ; D2_ADC2.1@5195,90.94 v1(5195,145) ; D3_AFE2.2@5834.53,542.01 5835,541.54 v1(5835,500)
  Top Layer w15: C14_ADC2.1@4795,556.5 4798.7,552.8 U6_ADC2.7@4858.86,552.8 v1@4907.2,552.8
  Top Layer w20: C52_PWR2.1@4185,637.91 4197.09,637.91 4210,625 4255,625 4305,625 4323.03,625 4330.55,632.52 4361.99,632.52 D18_PWR2.2@4370,640.53 v1(4370,685)
  Bottom Layer w10: v1(4060,202.13) 4179.88,202.13 4212.63,234.87 4280.13,234.87 4304.87,210.13 4727.37,210.13 4774.87,257.63 4774.87,282.37 4750,307.25 v1(4750,315) 4782.38,347.38 4803.87,347.38 4843.75,387.26 4843.75,586.25 4690.13,739.87 4659.87,739.87 4585,665 4445,665 4425,685 v1(4370,685) ; v1(4330,885) 4301.77,856.77 4301.77,824.02 4295.13,817.37 4295.13,709.87 4320,685 v1(4370,685) ; v1(4715,650) 4437.45,650 4421.58,665.87 4389.13,665.87 v1(4370,685) ; v1(4915,555) 4915,565 4695,785 4608.51,785 4596.94,773.43 4543.09,773.43 4509.54,739.87 4385.13,739.87 4385,740 4375,730 4375,707.75 4370,702.75 v1(4370,685) ; v1(5560,960) 5585,935 5585,525 5605,505 5835,505 5814.87,484.87 5814.87,69.87 5800,55 5345,55 5260,140 5200,140 v1(5195,145) 5190.13,140.13 5190.13,229.87 5149.87,270.13 5132.63,270.13 5115.13,287.63 5115.13,304.87 4954.87,465.13 4897.63,465.13 4880.13,482.63 4880.13,574.87 4685,770 4660,770 4580,690 4445,690 4430,705 4390,705 v1(4370,685)
CAPE_A0: J8.12 R28.2 U7.2 | length 2954.2
  Top Layer w10: U7.2@527.22,473.95 527.22,517.22 562.25,552.25 562.53,552.25 596.28,586 596.28,586.28 602.02,592.02 602.02,702.02 672.13,772.13 821.9,772.13 852.87,803.1 852.87,1546.9 689.77,1710 490,1710 475,1725 475,1820 523.27,1868.27 639.92,1868.27 666.65,1895 1270.5,1895 1292.87,1917.38 1292.87,1917.87 1325,1950 1325,2025 J8.12@1275,2075 ; U7.2@527.2,492.24 527.2,446.42 R28.2@538.62,435
CAPE_A1: J8.11 R32.2 U7.6 | length 2597.6
  Top Layer w10: U7.6@552.8,647.76 552.8,704.17 R32.2@555,706.38 571.38,706.38 655,790 814.5,790 835,810.5 835,1539.5 684.5,1690 475,1690 455,1710 455,1840 501.14,1886.14 632.52,1886.14 661.38,1915 1265.22,1915 1275,1924.78 J8.11@1275,1975
DGND: C2_ADC1.2 C2_ADC2.2 C3_ADC1.2 C3_ADC2.2 C31.2 C32.2 C33.2 C34.2 C35.2 C37.2 C38.2 C39.2 C53_PWR1.2 C53_PWR2.2 C54_PWR1.2 C54_PWR2.2 C55_PWR1.2 C55_PWR2.2 C57_PWR1.2 C57_PWR2.2 C60_PWR1.2 C60_PWR2.2 C61_PWR1.2 C61_PWR2.2 J2.2 J3_HART1.7 J3_HART1.9 J3_HART2.7 J3_HART2.9 J8.1 J8.2 J9.1 J9.2 J9.43 J9.44 J9.45 J9.46 Q1.2 R42.1 R43.2 R44.1 R45.1 R67_PWR1.1 R67_PWR2.1 R68_PWR1.1 R68_PWR2.1 S1.1 S1.2 TP3.1 TP8.1 U1_ADC1.2 U1_ADC1.8 U1_ADC2.2 U1_ADC2.8 U4_ADC1.3 U4_ADC2.3 U7.4 U8.2 U9.2 U10.1 U10.11 U11.4 U11.7 U15_PWR1.1 U15_PWR1.9 U15_PWR2.1 U15_PWR2.9 | length 3627.4
  Top Layer w6: v1(920,870) R45.1@920,911.38 ; v1(2310,515) J3_HART2.7@2392.48,515 ; v1@2825,1595 2831.38,1588.62 R68_PWR1.1@2831.38,1540 ; 2830.01,527.26 v1(2809.73,527.26) 2809.73,501.65 R68_PWR2.1@2831.38,480 ; v1(3215,845) 3222.82,852.82 U1_ADC2.8@3272.72,852.82 ; v1(3215,1915) 3222.82,1922.82 U1_ADC1.8@3272.72,1922.82
  Top Layer w10: S1.1@105,310 S1.2@105,260 v1(155,260) v1@160.03,260 ; U11.7@162.8,582.2 212.2,582.2 220,590 v1(230,590) ; C34.2@288.64,715.01 295,708.65 295,690 351.61,633.39 U11.4@387.2,633.39 ; C34.2@296.53,715 v1(330,715) ; C31.2@455,693.62 v1(455,740) ; U7.4@578.39,492.24 578.39,498.39 605,525 v1(610,525) ; v1(645,455) 650,455 U9.2@690.72,455.02 ; v1(645,615) U8.2@690.71,615 ; C32.2@845.02,486.51 893.52,486.51 v1@895.02,485.02 ; C33.2@845.02,646.51 893.52,646.51 v1@895.02,645.01 ; R42.1@1135,1041.38 1136.97,1039.41 1183.5,1039.41 1185,1037.91 1180,1032.91 v1(1180,1000) ; C35.2@1365,1326.93 v1(1365,1375) ; U10.1@1399.72,1114.37 1399.72,1124.72 1445,1170 C38.2@1476.38,1170 ; v1(1410,885) R43.2@1410,926.38 ; v1(1475,870) C37.2@1475,918.5 ; v1(1540,885) R44.1@1540,926.38 ; v1(1620,895) C39.2@1620,947.91 ; v1(2310,1535) J3_HART1.9@2392.48,1535 J3_HART1.7@2392.48,1585 ; J3_HART2.9@2392.48,465 J3_HART2.7@2392.48,515 ; v1(2720,615) C54_PWR2.2@2720,648.5 ; v1(2720,1685) C54_PWR1.2@2720,1718.5 ; v1(2780,595) 2780,597.76 2781.38,596.38 R67_PWR2.1@2781.38,635 ; v1(2780,1665) 2780,1667.76 2781.38,1666.38 R67_PWR1.1@2781.38,1705 ; U15_PWR2.9@3025,685 U15_PWR2.9@3027.24,687.24 ; U15_PWR1.9@3025,1745 U15_PWR1.9@3027.24,1747.24 ; v1(3085,795) C3_ADC2.2@3126.38,795 ; v1(3085,2050) 3086.38,2050 C2_ADC1.2@3126.38,2090 ; v1(3090,1020) C2_ADC2.2@3126.38,1020 3120.13,1013.75 3120.13,967.63 3126.38,961.37 3126.38,936.26 U4_ADC2.3@3124.41,934.29 ; v1(3120,1960) 3120,1975 3124.41,1979.41 U4_ADC1.3@3124.41,2004.29 U4_ADC1.3@3126.38,2006.26 ; v1(3125,1825) 3125,1863.62 C3_ADC1.2@3126.38,1865 ; v1(3215,1020) 3215,1015 3235.52,1015 3243.45,1007.07 3245.46,1007.07 3247.53,1005 3270.53,1005 U1_ADC2.2@3272.72,1002.82 ; v1(3215,2085) 3227.18,2072.82 U1_ADC1.2@3272.72,2072.82 ; C61_PWR1.2@3293.09,1835 3308.09,1850 C61_PWR1.2@3313.09,1845
  Top Layer w20: v1(2635,575) C53_PWR2.2@2635,627.91 ; v1(2635,1645) C53_PWR1.2@2635,1697.91 ; v1(2809.73,527.26) 2860.76,527.26 C60_PWR2.2@2868.5,535 2870,536.5 2870,580 2930.79,640.79 v2(2930.79,660) U15_PWR2.9@2980,660 3000,660 U15_PWR2.9@3025,685 ; v1@2825,1595 C60_PWR1.2@2868.5,1595 2870,1596.5 2870,1640 2930.79,1700.79 v2(2930.79,1720) U15_PWR1.9@2980,1720 3000,1720 U15_PWR1.9@3025,1745 ; v1(2880,320) C57_PWR2.2@2907.91,320 ; v1(2880,365) 2912.91,365 C57_PWR2.2@2932.91,345 ; v1(2880,1380) C57_PWR1.2@2907.91,1380 ; v1(2880,1425) 2912.91,1425 C57_PWR1.2@2932.91,1405 C57_PWR1.2@2923.09,1405 ; C57_PWR2.2@2923.07,320 C57_PWR2.2@2948.07,345 ; C57_PWR1.2@2929.67,1382.13 C57_PWR1.2@2934.67,1387.13 ; v1(3000,840) 3042.24,840 3042.24,834.84 C55_PWR2.2@3052.09,825 ; v1(3000,1880) 3042.24,1880 3042.24,1874.84 C55_PWR1.2@3052.09,1865 3027.24,1840.16 U15_PWR1.1@3027.24,1794.8 ; U15_PWR2.9@3027.24,687.24 U15_PWR2.1@3027.24,734.8 ; U15_PWR1.9@3027.24,1747.24 U15_PWR1.1@3027.24,1794.8 ; v1(3060,1795) 3027.44,1795 U15_PWR1.1@3027.24,1794.8 ; v1(3265,765) C61_PWR2.2@3313.09,765 ; v1(3265,1835) C61_PWR1.2@3293.09,1835
  other v1: 885,490 885,645 1420,1145 2820,1595
  other v2: 2980,630.87 3029.21,660 2980,689.13 1445,1045.47 1445,1104.53 2980,1690.87 3029.21,1720 2980,1749.13
DVDD: C2_ADC1.1 C2_ADC2.1 C3_ADC1.1 C3_ADC2.1 C31.1 C32.1 C33.1 C34.1 J3_HART1.5 J3_HART2.5 J9.3 J9.4 R28.1 R29.1 R32.1 R33.1 R34.1 R35.1 R36.1 R37.1 R38.1 TP10.1 U1_ADC1.1 U1_ADC1.7 U1_ADC2.1 U1_ADC2.7 U4_ADC1.5 U4_ADC2.5 U7.8 U8.5 U9.5 U11.8 | length 2227.8
  Top Layer w6: U4_ADC2.5@3175.59,845.71 3176.29,845.71 3203.83,873.25 3232.29,873.25 3236.91,877.87 3272.72,877.87 U1_ADC2.7@3272.72,877.82 ; U4_ADC1.5@3175.59,1915.71 3176.29,1915.71 3176.29,1920.71 3203.45,1947.87 3272.72,1947.87 U1_ADC1.7@3272.72,1947.82
  Top Layer w10: v1(125,380) R38.1@125,413.5 ; U11.8@162.8,556.61 238.86,556.61 259.87,577.63 259.87,602.37 249.87,612.37 249.87,715.01 C34.1@241.39,715.01 ; v1@185.01,715.01 C34.1@233.52,715.01 ; R37.1@200.02,413.52 275.01,413.52 v1@275.01,370.02 ; v1@350.01,370.02 R34.1@350.01,413.52 ; v1@425.02,370.02 R35.1@425.02,413.52 ; R35.1@425.02,421.39 477.77,421.39 R28.1@491.38,435 ; U7.8@501.61,647.76 501.61,687.99 ; C31.1@503.62,700 503.62,733.62 523.62,753.62 R32.1@555,753.62 ; R29.1@703.52,715.01 703.52,690.8 745,649.32 745,633.25 749.69,628.57 758.38,619.84 763.24,615.01 813.52,615.01 845.02,583.52 893.52,583.52 v1@895.02,585.01 ; R33.1@758.62,355 749.7,363.92 749.7,441.48 763.24,455.02 U9.5@779.31,455.02 813.52,455.02 845.02,423.52 v1@893.52,423.52 ; v1(2310,565) J3_HART2.5@2392.48,565 ; v1(2310,1625) 2320,1635 J3_HART1.5@2392.48,1635 ; v1(3085,2100) 3100,2115 3148.62,2115 C2_ADC1.1@3173.62,2090 3185.13,2101.5 3185.13,2102.37 3197.75,2115 3255.53,2115 U1_ADC1.1@3272.72,2097.82 ; v1(3150,1060) 3173.62,1036.38 C2_ADC2.1@3173.62,1030 ; C2_ADC2.1@3175,1030 3182.75,1030 3202.63,1049.87 3203.5,1049.87 3203.62,1050 3250.53,1050 U1_ADC2.1@3272.72,1027.82 ; U4_ADC2.5@3175.59,845.71 3175.59,796.97 C3_ADC2.1@3173.62,795 v1(3215,795) ; U4_ADC1.5@3175.59,1915.71 3175.59,1866.97 C3_ADC1.1@3173.62,1865 v1(3215,1865)
  other v1: 275,375 350,375 425,375 885,425 885,585 195,715 505,740
DVDD_ISO_ADC1: C1_ADC1.1 C4_ADC1.1 C6_ADC1.1 C7_ADC1.1 C44_PWR1.1 D14_PWR1.2 D15_PWR1.1 R1_ADC1.1 R2_ADC1.1 R3_ADC1.1 R6_ADC1.2 R10_ADC1.1 TP1_ADC1.1 U1_ADC1.10 U1_ADC1.16 U2_ADC1.8 U6_ADC1.19 U13_PWR1.3 | length 1575.1
  Top Layer w6: U1_ADC1.10@3487.28,1948.19 U1_ADC1.10@3487.28,1947.82 3522.94,1947.82 3523.51,1947.25 3552.75,1947.25 v1(3585,1915) ; R3_ADC1.1@3793.62,1940 v1@3840,1940
  Top Layer w10: U1_ADC1.16@3487.28,2097.82 3515.25,2097.82 3527.63,2110.19 3566.19,2110.19 C1_ADC1.1@3586.38,2090 3586.38,2083.62 3620,2050 v1(3635,2050) ; v1(3705,2040) R2_ADC1.1@3746.38,2040 ; v1@3840,1940 C4_ADC1.1@3881.38,1940 3881.38,1999.09 U2_ADC1.8@3878.86,2001.61 ; R1_ADC1.1@4233.62,1895 4260,1895 v1(4270,1905) ; R6_ADC1.2@4233.62,2090 4238.62,2085 4255,2085 4266.81,2073.19 4268.62,2075 v1(4275,2075) ; v1(4715,1310) 4714.17,1310 4709.17,1305 4705.75,1308.43 4813.52,1308.43 4845.1,1340 C6_ADC1.1@4851.5,1340 ; D14_PWR1.2@4825,1135.94 4829.06,1140 v1(4885,1140) ; C6_ADC1.1@4856.3,1338.99 4879.92,1362.62 4911.3,1362.62 4910,1363.91 4910,1420.09 5005,1515.09 5005,1530 5021.02,1546.02 U6_ADC1.19@5091.14,1546.02 ; R10_ADC1.1@5025,2003.62 5025,2025 v1(5050,2050) v1@5050,2053.62
  Top Layer w20: U13_PWR1.3@3972.4,1325.87 4092.95,1325.87 C44_PWR1.1@4152.09,1385 D15_PWR1.1@4245.53,1385 v1(4290,1385)
  other v1: 3835,1945
DVDD_ISO_ADC2: C1_ADC2.1 C4_ADC2.1 C6_ADC2.1 C7_ADC2.1 C44_PWR2.1 D14_PWR2.2 D15_PWR2.1 R1_ADC2.1 R2_ADC2.1 R3_ADC2.1 R6_ADC2.2 R10_ADC2.1 TP1_ADC2.1 U1_ADC2.10 U1_ADC2.16 U2_ADC2.8 U6_ADC2.19 U13_PWR2.3 | length 1574.2
  Top Layer w6: U1_ADC2.10@3487.28,878.19 U1_ADC2.10@3487.28,877.82 3522.94,877.82 3523.51,877.25 3552.75,877.25 v1(3585,845) ; R3_ADC2.1@3793.62,870 v1@3840,870
  Top Layer w10: U1_ADC2.16@3487.28,1027.82 3515.25,1027.82 3527.63,1040.19 3566.19,1040.19 C1_ADC2.1@3586.38,1020 3586.38,1013.62 3620,980 v1(3635,980) ; v1(3705,970) R2_ADC2.1@3746.38,970 ; v1@3840,870 C4_ADC2.1@3881.38,870 ; U2_ADC2.8@3878.86,929.36 3881.38,926.84 C4_ADC2.1@3881.38,867.74 ; R1_ADC2.1@4233.62,825 4260,825 v1(4270,835) ; R6_ADC2.2@4233.62,1017.74 4236.37,1015 4255,1015 4266.81,1003.19 4268.62,1005 v1(4275,1005) ; v1(4715,240) 4714.17,240 4709.17,235 4705.75,238.43 4813.52,238.43 4845.1,270 C6_ADC2.1@4851.5,270 ; D14_PWR2.2@4825,65.94 4829.06,70 v1(4885,70) ; C6_ADC2.1@4856.3,268.99 4879.92,292.62 4911.3,292.62 4910,293.91 4910,350.09 5005,445.09 5005,460 5021.02,476.02 U6_ADC2.19@5091.14,476.02 ; R10_ADC2.1@5025,933.62 5025,955 v1(5050,980) v1@5050,983.62
  Top Layer w20: U13_PWR2.3@3972.4,255.87 4092.95,255.87 C44_PWR2.1@4152.09,315 v1(4290,315)
  other v1: 3835,875
GND_ADC1: C1_ADC1.2 C4_ADC1.2 C6_ADC1.2 C7_ADC1.2 C8_ADC1.2 C12_ADC1.2 C13_ADC1.2 C14_ADC1.2 C16_ADC1.2 C17_AFE1.2 C19_AFE1.1 C20_AFE1.2 C21_AFE1.2 C22_AFE1.2 C23_AFE1.2 C25_AFE1.1 C27_AFE1.2 C28_AFE1.2 C30_AFE1.1 C40_PWR1.2 C41_PWR1.2 C43_PWR1.2 C44_PWR1.2 C46_PWR1.2 C47_PWR1.2 C48_PWR1.2 C52_PWR1.2 C58_PWR1.2 C59_PWR1.2 C61_PWR1.1 D9_AFE1.B1 D9_AFE1.B2 D13_PWR1.1 D15_PWR1.2 D17_PWR1.2 D18_PWR1.1 D100_AFE1.B1 D100_AFE1.B2 D103_AFE1.B1 D103_AFE1.B2 J1_AFE1.4 J4_HART1.3 J4_HART1.4 J4_HART1.8 Q3_PWR1.2 Q4_PWR1.2 R7_ADC1.1 R8_ADC1.2 R9_ADC1.1 R19_AFE1.1 R27_AFE1.1 R50_PWR1.1 R53_PWR1.1 R54_PWR1.2 R56_PWR1.1 R69_PWR1.1 T1_PWR1.7 T1_PWR1.9 T1_PWR1.12 TP4_AFE1.1 TP5_AFE1.1 TP6_AFE1.1 U1_ADC1.9 U1_ADC1.15 U2_ADC1.4 U6_ADC1.9 U6_ADC1.18 U12_PWR1.4 U12_PWR1.9 U13_PWR1.1 U14_PWR1.4 U14_PWR1.9 U16_PWR1.4 U16_PWR1.9 | length 4354.9
  Top Layer w6: D17_PWR1.2@4370,1624.47 4389.47,1624.47 4424.07,1659.07 4424.13,1659.07 4430.5,1665.44 4467.92,1665.44 J4_HART1.3@4492.48,1690 J4_HART1.4@4627.52,1690 4652.08,1665.44 4689.5,1665.44 4695.87,1659.07 4695.87,1620.93 4689.5,1614.56 4652.08,1614.56 J4_HART1.8@4627.52,1590 ; R27_AFE1.1@5138.62,1812.76 5145,1819.13 v1(5145,1850) ; 5607.48,1380 5620,1380 5650,1410 5720,1410 5735,1425 R19_AFE1.1@5760.63,1425 ; v1(5710,1500) 5705,1505 5710,1510 C21_AFE1.2@5760,1510
  Top Layer w10: U1_ADC1.9@3487.28,1922.82 3537.5,1922.82 3535,1920.32 v1(3535,1915) ; U1_ADC1.15@3487.28,2072.82 3527.5,2072.82 3540,2085.32 v4(3540,2080.32) ; v1@3607.95,1282.05 v1(3610,1280) ; C1_ADC1.2@3633.62,2090 v1(3705,2090) R8_ADC1.2@3746.38,2090 ; v1(3705,1990) R7_ADC1.1@3746.38,1990 ; D13_PWR1.1@3712.6,1225.59 3712.6,1252.6 3720,1260 v1(3790,1260) 3820,1260 3840,1240 3871.86,1271.86 C41_PWR1.2@3871.86,1252.9 3907.1,1252.9 3915,1245 3915,1205 3940.59,1179.41 Q3_PWR1.2@3958.5,1179.41 ; v1(3730,1565) 3730,1615 3750,1635 C47_PWR1.2@3750,1617.09 ; v1(3730,1780) 3730,1815 3754.59,1839.59 3762.09,1832.09 C58_PWR1.2@3750,1832.09 ; C43_PWR1.2@3840,1411.5 3835,1416.5 3840,1421.5 v1(3840,1465) ; U16_PWR1.9@3885,1775 v2(3904.69,1794.68) ; U13_PWR1.1@3897.6,1325.87 3890,1325.87 3874.13,1310 v1(3855,1310) ; C4_ADC1.2@3928.62,1940 3970,1940 v1(3970,1945) ; C44_PWR1.2@4037.91,1385 v1(4090,1385) ; v1(4055,2085) 4060,2085 4066.61,2078.39 U2_ADC1.4@4111.14,2078.39 ; R56_PWR1.1@4103.62,1615 C46_PWR1.2@4170,1615 ; R69_PWR1.1@4110,1736.38 4110,1746.38 4156.38,1746.38 4185,1775 C52_PWR1.2@4185,1822.09 ; v1(4130,1655) 4135,1655 4135,1650 C46_PWR1.2@4170,1615 ; C46_PWR1.2@4185,1607.09 4182.91,1607.09 4175,1615 C46_PWR1.2@4170,1615 ; C46_PWR1.2@4190,1612.09 4235.59,1566.5 Q4_PWR1.2@4254.41,1566.5 ; R9_ADC1.1@4233.62,2040 4255,2040 v1@4270,2025 ; U12_PWR1.4@4252.6,1238.39 4251.61,1238.39 4255,1241.77 v1(4255,1275) ; v1@4269.31,2025.69 4275,2031.38 v1(4275,2030) ; v1(4330,1210) C40_PWR1.2@4330,1266.93 4356.93,1266.93 4373.62,1283.62 R53_PWR1.1@4400,1283.62 R53_PWR1.1@4393.62,1290 ; v1(4345,1790) 4345,1814.47 D18_PWR1.1@4370,1839.47 ; v1(4365,1580) 4365,1619.47 D17_PWR1.2@4370,1624.47 ; D15_PWR1.2@4374.47,1385 v1(4420,1385) ; v1(4720,1990) 4755,1990 C28_AFE1.2@4770,2005 C28_AFE1.2@4775,2005 ; v1(4741.09,1343.13) 4785.38,1343.13 C6_ADC1.2@4788.5,1340 ; v1(4910,1280) 4910,1314.07 C7_ADC1.2@4911.3,1315.37 ; C30_AFE1.1@4950,2015 4950,2005 C30_AFE1.1@4955,2005 v1(4955,2060) ; R50_PWR1.1@4958.62,1195 R54_PWR1.2@4958.62,1240 4960,1238.62 5003.62,1238.62 v1(5005,1240) ; C16_ADC1.2@4965,1298.5 5006.5,1298.5 v1(5010,1295) ; v1(5038.9,1516.15) 5038.9,1518.9 5040.43,1520.43 U6_ADC1.18@5091.14,1520.43 ; v1(5045,1150) C12_ADC1.2@5045,1191.38 ; v1(5095,1150) C13_ADC1.2@5095,1191.38 ; C25_AFE1.1@5350.01,1760.01 C25_AFE1.1@5370,1780 ; C17_AFE1.2@5364.45,1463.52 5364.45,1470 C17_AFE1.2@5364.45,1473.52 ; C19_AFE1.1@5364.45,1573.52 C19_AFE1.1@5364.45,1578.49 ; C17_AFE1.2@5365,1485 5420,1485 v1(5420,1490) ; C19_AFE1.1@5365,1565 5420,1565 v1(5420,1560) ; C22_AFE1.2@5365,1660 5370.03,1654.97 5370.03,1640 5380.03,1650 5385.03,1645 v1(5420,1645) ; C25_AFE1.1@5365,1760 5370,1760 5385,1775 v1(5420,1775) ; D9_AFE1.B1@5601.16,1504.16 D9_AFE1.B2@5620.84,1504.16 ; D103_AFE1.B2@5924.27,1909.25 D103_AFE1.B1@5943.95,1909.25 ; v1(6040,1435) C20_AFE1.2@6095,1435 ; v1(3855,1310) 3854.57,1309.57 3855,1309.13 v1(3855,1310)
  Top Layer w15: v1(3550,1720) 3551.85,1721.85 T1_PWR1.12@3607.95,1721.85 ; U14_PWR1.9@3885,1560 3923.39,1598.39 U14_PWR1.4@3940.12,1598.39 ; 3897.8,1619.06 3908.62,1629.88 C48_PWR1.2@3908.62,1670 ; 3897.8,1834.06 3908.62,1844.88 C59_PWR1.2@3908.62,1875 ; v2(3904.69,1794.68) 3923.39,1813.39 U16_PWR1.4@3940.12,1813.39 ; C8_ADC1.2@4735,1563.5 C14_ADC1.2@4795,1563.5 4803.11,1571.61 U6_ADC1.9@4858.86,1571.61 4903.39,1571.61 4910,1565 v1(4915,1565) ; 6109,1288 6150.45,1288
  Top Layer w20: C61_PWR1.1@3446.95,1845 3456.95,1835 v1(3495,1835) ; v1@3607.95,1282.05 T1_PWR1.7@3607.95,1328.15 ; T1_PWR1.9@3607.95,1485.63 3614.37,1485.63 3655,1445 3655,1447.49 3657.49,1445 v1(3660,1445) ; v1(5525,1675) C23_AFE1.2@5575,1675 ; v1(5525,1755) C27_AFE1.2@5575,1755 ; v1(5565,1380) 5607.48,1380
  other v1: 6134,1255 4185,1770
  other v2: 4137.83,1170.87 4192.17,1170.87 4165,1200 4137.83,1229.13 4192.17,1229.13 3865.31,1540.32 3904.69,1540.32 3865.31,1579.68 3904.69,1579.68 3865.31,1755.32 3904.69,1755.32 3865.31,1794.68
